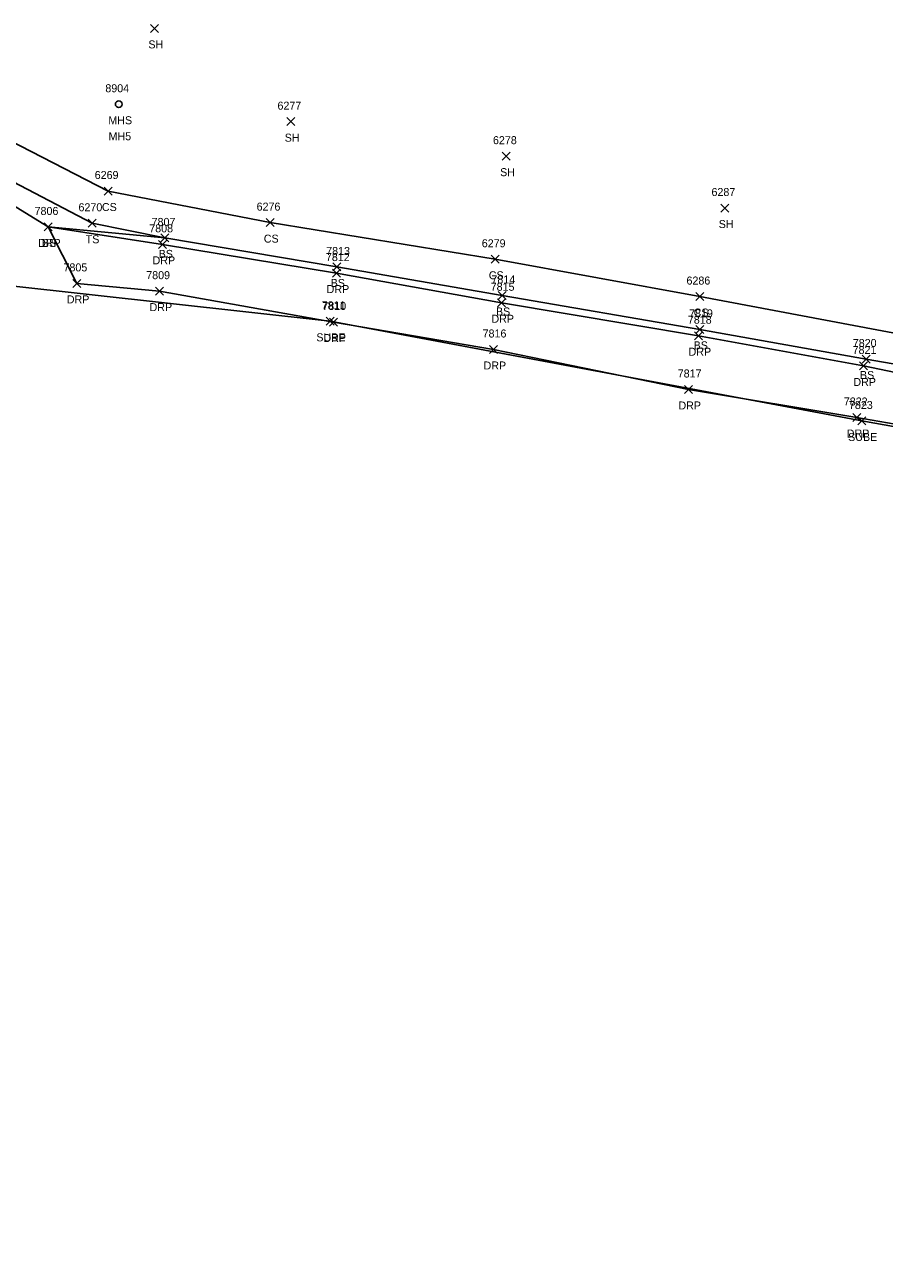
# Model space of a CAD drawing. Extents: x 1678863 to 1683592, y 407783 to 418211.
# Drawn here: x 1679783.6 to 1679998.6, y 409178.5 to 409483.2 of the extents above; entities that cross this region are included whole.
import ezdxf

# ---------------------------------------------------------------- set-up
doc = ezdxf.new("R2010")
doc.units = 0
for name, color, linetype in [('L_A', 7, 'Continuous'), ('L_I', 7, 'Continuous'), ('L_TIC', 7, 'Continuous'), ('LELB', 7, 'Continuous'), ('R_A', 7, 'Continuous'), ('R_I', 7, 'Continuous'), ('R_TIC', 7, 'Continuous'), ('RDG', 7, 'Continuous'), ('RDP', 7, 'Continuous'), ('U_A', 7, 'Continuous'), ('U_C', 7, 'Continuous'), ('U_I', 7, 'Continuous'), ('U_TIC', 7, 'Continuous'), ('UE', 7, 'Continuous'), ('USMH', 7, 'Continuous')]:
    doc.layers.add(name, color=color, linetype=linetype)

msp = doc.modelspace()

# ---------------------------------------------------------------- linework, layer by layer
at = {"layer": 'L_TIC'}
for points in [[(1679815.06, 409481.24), (1679817.06, 409483.24)], [(1679817.06, 409481.24), (1679815.06, 409483.24)], [(1679849.14, 409457.93), (1679851.14, 409459.93)], [(1679851.14, 409457.93), (1679849.14, 409459.93)], [(1679903, 409449.3), (1679905, 409451.3)], [(1679905, 409449.3), (1679903, 409451.3)], [(1679803.5, 409440.59), (1679805.5, 409442.59)], [(1679805.5, 409440.59), (1679803.5, 409442.59)], [(1679957.62, 409436.34), (1679959.62, 409438.34)], [(1679959.62, 409436.34), (1679957.62, 409438.34)], [(1679799.48, 409432.53), (1679801.48, 409434.53)], [(1679801.48, 409432.53), (1679799.48, 409434.53)], [(1679843.97, 409432.69), (1679845.97, 409434.69)], [(1679845.97, 409432.69), (1679843.97, 409434.69)], [(1679788.5, 409431.61), (1679790.5, 409433.61)], [(1679790.5, 409431.61), (1679788.5, 409433.61)], [(1679817.69, 409428.87), (1679819.69, 409430.87)], [(1679819.69, 409428.87), (1679817.69, 409430.87)], [(1679900.21, 409423.53), (1679902.21, 409425.53)], [(1679902.21, 409423.53), (1679900.21, 409425.53)], [(1679860.69, 409421.61), (1679862.69, 409423.61)], [(1679862.69, 409421.61), (1679860.69, 409423.61)], [(1679902, 409414.48), (1679904, 409416.48)], [(1679904, 409414.48), (1679902, 409416.48)], [(1679951.43, 409414.21), (1679953.43, 409416.21)], [(1679953.43, 409414.21), (1679951.43, 409416.21)], [(1679951.41, 409406.01), (1679953.41, 409408.01)], [(1679953.41, 409406.01), (1679951.41, 409408.01)], [(1679992.98, 409398.6), (1679994.98, 409400.6)], [(1679994.98, 409398.6), (1679992.98, 409400.6)]]:
    msp.add_lwpolyline(points, dxfattribs=at)
at = {"layer": 'LELB'}
for points in [[(1679776.94, 409455.73), (1679804.5, 409441.59), (1679844.97, 409433.69), (1679901.21, 409424.53), (1679952.43, 409415.21), (1680003.72, 409405.57), (1680059.02, 409394.1), (1680110.99, 409385.82), (1680158.4, 409378.08), (1680184.18, 409376.34)], [(1679773.55, 409447.6), (1679800.48, 409433.53)], [(1679789.5, 409432.61), (1679818.69, 409429.87), (1679861.69, 409422.61), (1679903, 409415.48), (1679952.41, 409407.01), (1679993.98, 409399.6), (1680039.22, 409391.75), (1680088.29, 409381.26)], [(1679800.48, 409433.53), (1679818.69, 409429.87)]]:
    msp.add_lwpolyline(points, dxfattribs=at)
at = {"layer": 'R_TIC'}
for points in [[(1679788.5, 409431.61), (1679790.5, 409433.61)], [(1679790.5, 409431.61), (1679788.5, 409433.61)], [(1679817.11, 409427.26), (1679819.11, 409429.26)], [(1679819.11, 409427.26), (1679817.11, 409429.26)], [(1679860.62, 409420.08), (1679862.62, 409422.08)], [(1679862.62, 409420.08), (1679860.62, 409422.08)], [(1679795.68, 409417.5), (1679797.68, 409419.5)], [(1679797.68, 409417.5), (1679795.68, 409419.5)], [(1679795.68, 409417.5), (1679797.68, 409419.5)], [(1679797.68, 409417.5), (1679795.68, 409419.5)], [(1679816.36, 409415.56), (1679818.36, 409417.56)], [(1679818.36, 409415.56), (1679816.36, 409417.56)], [(1679901.81, 409412.66), (1679903.81, 409414.66)], [(1679903.81, 409412.66), (1679901.81, 409414.66)], [(1679859.83, 409407.85), (1679861.83, 409409.85)], [(1679861.83, 409407.85), (1679859.83, 409409.85)], [(1679951.09, 409404.42), (1679953.09, 409406.42)], [(1679953.09, 409404.42), (1679951.09, 409406.42)], [(1679899.85, 409400.98), (1679901.85, 409402.98)], [(1679901.85, 409400.98), (1679899.85, 409402.98)], [(1679992.29, 409396.86), (1679994.29, 409398.86)], [(1679994.29, 409396.86), (1679992.29, 409398.86)], [(1679948.56, 409390.98), (1679950.56, 409392.98)], [(1679950.56, 409390.98), (1679948.56, 409392.98)], [(1679990.64, 409383.98), (1679992.64, 409385.98)], [(1679992.64, 409383.98), (1679990.64, 409385.98)]]:
    msp.add_lwpolyline(points, dxfattribs=at)
at = {"layer": 'RDG'}
msp.add_lwpolyline([(1679771.23, 409443.84), (1679789.5, 409432.61)], dxfattribs=at)
at = {"layer": 'RDP'}
for points in [[(1679796.68, 409418.5), (1679789.5, 409432.61), (1679818.11, 409428.26), (1679861.62, 409421.08), (1679902.81, 409413.66), (1679952.09, 409405.42), (1679993.29, 409397.86), (1680038.06, 409388.6), (1680087.08, 409379.32), (1680085.49, 409369.3), (1680079.83, 409363.97), (1680081.83, 409335.2), (1680083.52, 409293.99), (1680083.78, 409252.21), (1680087.56, 409206.32), (1680095.41, 409184.98)], [(1679796.68, 409418.5), (1679817.36, 409416.56), (1679860.83, 409408.85), (1679900.85, 409401.98), (1679949.56, 409391.98), (1679991.64, 409384.98), (1680035.68, 409377.31), (1680044.5, 409371.05), (1680053.86, 409361.69), (1680068.07, 409330.8), (1680071.91, 409293.7), (1680071.66, 409253.14), (1680075.61, 409203.9), (1680080.62, 409178.48), (1680095.41, 409184.98)]]:
    msp.add_lwpolyline(points, dxfattribs=at)
at = {"layer": 'U_TIC'}
for points in [[(1679859.01, 409408.02), (1679861.01, 409410.02)], [(1679861.01, 409408.02), (1679859.01, 409410.02)], [(1679991.93, 409383.11), (1679993.93, 409385.11)], [(1679993.93, 409383.11), (1679991.93, 409385.11)]]:
    msp.add_lwpolyline(points, dxfattribs=at)
at = {"layer": 'UE'}
msp.add_lwpolyline([(1679647.13, 409474.1), (1679706.97, 409442.12), (1679779.43, 409417.98), (1679860.01, 409409.02), (1679992.93, 409384.11), (1680024.94, 409378.43), (1680045.36, 409367.07), (1680068.92, 409363.05), (1680092.68, 409364.94), (1680171.99, 409354.04), (1680191.1, 409351.39), (1680214.58, 409340.84), (1680248.48, 409278.96), (1680262.62, 409244.41), (1680272.9, 409222.87)], dxfattribs=at)
at = {"layer": 'USMH'}
for p, q in [((1679807.14, 409463.28), (1679807.14, 409463.28)), ((1679807.97, 409463.28), (1679807.97, 409463.28))]:
    msp.add_line(p, q, dxfattribs=at)
msp.add_circle((1679807.14, 409463.28), 0.833, dxfattribs=at)

# ---------------------------------------------------------------- texts
at = {"layer": 'L_A'}
for s, p in [('SH', (1679814.55, 409477.24)), ('SH', (1679848.63, 409453.93)), ('SH', (1679902.48, 409445.3)), ('CS', (1679802.94, 409436.59)), ('SH', (1679957.11, 409432.34)), ('BS', (1679787.94, 409427.61)), ('TS', (1679798.89, 409428.53)), ('CS', (1679843.41, 409428.69)), ('BS', (1679817.13, 409424.87)), ('BS', (1679860.13, 409417.61)), ('CS', (1679899.65, 409419.53)), ('BS', (1679901.44, 409410.48)), ('CS', (1679950.87, 409410.21)), ('BS', (1679950.85, 409402.01)), ('BS', (1679992.42, 409394.6))]:
    msp.add_text(s, height=2, dxfattribs=at).set_placement(p)
at = {"layer": 'L_I'}
for s, p in [('6277', (1679846.83, 409461.93)), ('6278', (1679900.69, 409453.3)), ('6269', (1679801.14, 409444.59)), ('6287', (1679955.31, 409440.34)), ('7806', (1679786.11, 409435.61)), ('6270', (1679797.09, 409436.53)), ('6276', (1679841.61, 409436.69)), ('7807', (1679815.36, 409432.87)), ('6279', (1679897.89, 409427.53)), ('7813', (1679859, 409425.61)), ('7814', (1679900.3, 409418.48)), ('6286', (1679949.06, 409418.21)), ('7819', (1679949.71, 409410.01)), ('7820', (1679990.63, 409402.6))]:
    msp.add_text(s, height=2, dxfattribs=at).set_placement(p)
at = {"layer": 'R_A'}
for p in [(1679786.99, 409427.61), (1679815.6, 409423.26), (1679859.11, 409416.08), (1679794.17, 409413.5), (1679794.17, 409413.5), (1679814.85, 409411.56), (1679900.3, 409408.66), (1679858.32, 409403.85), (1679949.58, 409400.42), (1679898.34, 409396.98), (1679990.77, 409392.86), (1679947.05, 409386.98), (1679989.12, 409379.98)]:
    msp.add_text('DRP', height=2, dxfattribs=at).set_placement(p)
at = {"layer": 'R_I'}
for s, p in [('7806', (1679786.11, 409435.61)), ('7808', (1679814.77, 409431.26)), ('7812', (1679858.93, 409424.08)), ('7805', (1679793.34, 409421.5)), ('7805', (1679793.34, 409421.5)), ('7809', (1679814.02, 409419.56)), ('7815', (1679900.12, 409416.66)), ('7810', (1679858.05, 409411.85)), ('7818', (1679949.4, 409408.42)), ('7816', (1679898.1, 409404.98)), ('7821', (1679990.59, 409400.86)), ('7817', (1679946.87, 409394.98)), ('7822', (1679988.38, 409387.98))]:
    msp.add_text(s, height=2, dxfattribs=at).set_placement(p)
at = {"layer": 'U_A'}
for s, p in [('MHS', (1679804.55, 409458.28)), ('SUBE', (1679856.54, 409404.02)), ('SUBE', (1679989.47, 409379.11))]:
    msp.add_text(s, height=2, dxfattribs=at).set_placement(p)
at = {"layer": 'U_C'}
msp.add_text('MH5', height=2, dxfattribs=at).set_placement((1679804.6, 409454.28))
at = {"layer": 'U_I'}
for s, p in [('8904', (1679803.8, 409466.28)), ('7811', (1679857.88, 409412.02)), ('7823', (1679989.67, 409387.11))]:
    msp.add_text(s, height=2, dxfattribs=at).set_placement(p)

doc.saveas('drawing.dxf')
